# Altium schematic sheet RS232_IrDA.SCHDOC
size A4; Revision: B.2
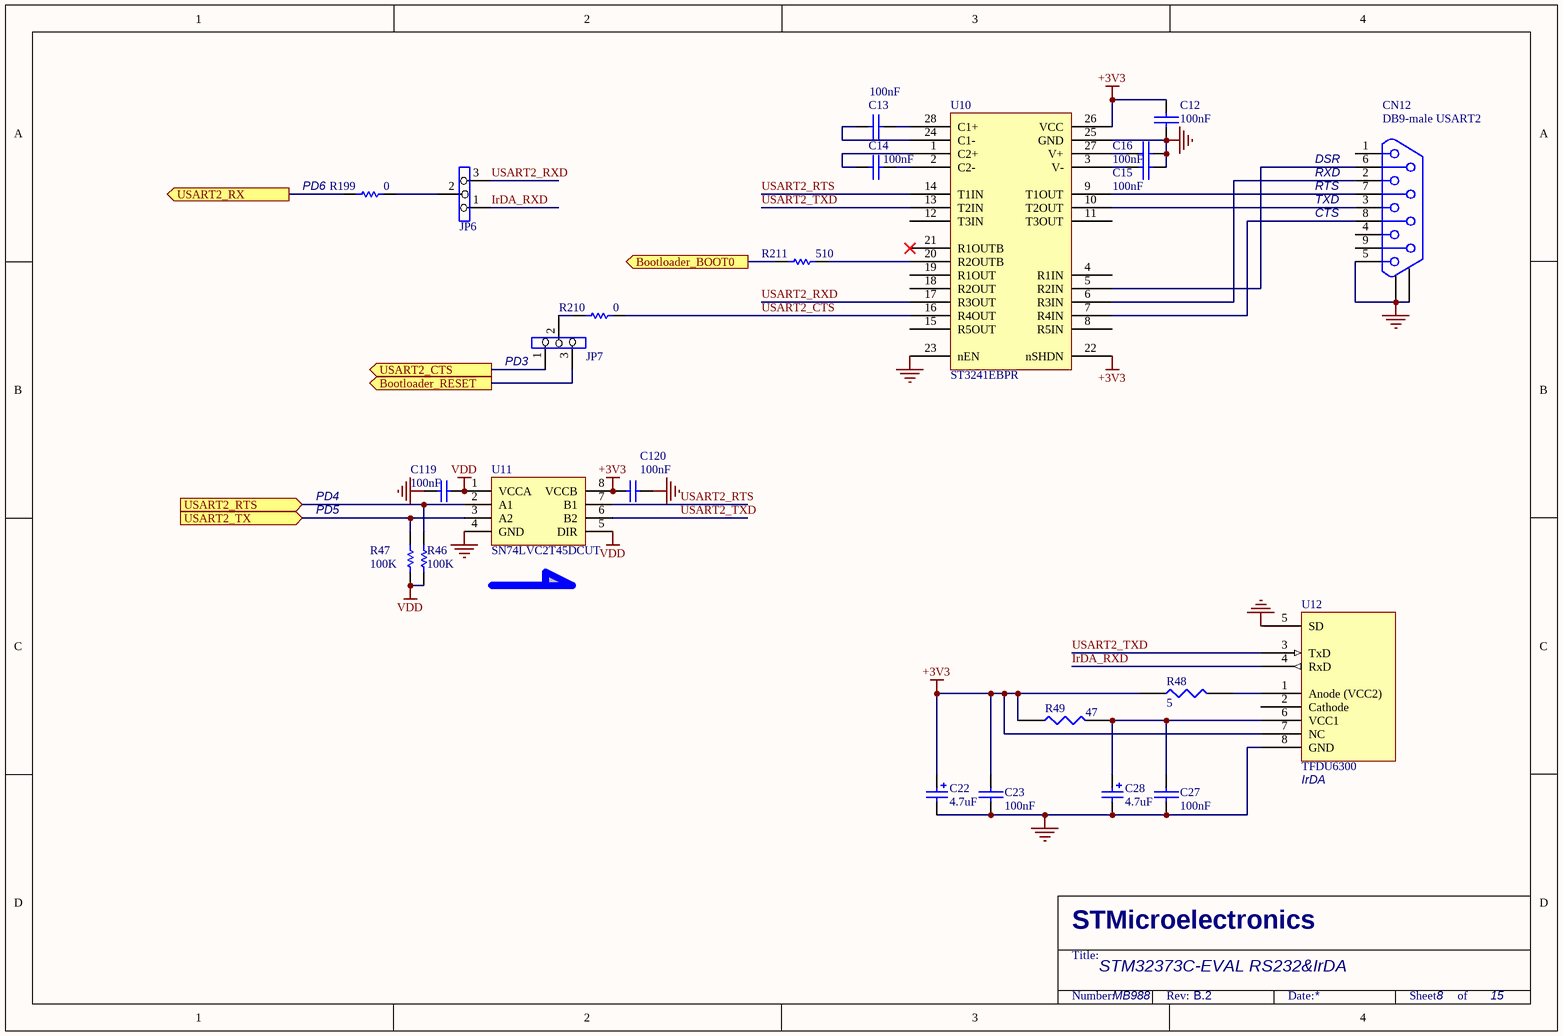
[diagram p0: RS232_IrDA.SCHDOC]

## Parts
C12  100nF  [0603C]
C13  100nF  [0603C]
C14  100nF  [0603C]
C15  100nF  [0603C]
C16  100nF  [0603C]
C22  4.7uF  [TAN-A]
C23  100nF  [0603C]
C27  100nF  [0603C]
C28  4.7uF  [TAN-A]
C119  100nF  [0603C]
C120  100nF  [0603C]
CN12  DB9-male USART2  [DB9/M]
JP6  (no value)  [SIP3]
JP7  (no value)  [SIP3]
R46  100K  [0603R]
R47  100K  [0603R]
R48  5  [0603R]
R49  47  [0603R]
R199  0  [0603R]
R210  0  [0603R]
R211  510  [0603R]
U10  ST3241EBPR  [SSOP28]
U11  SN74LVC2T45DCUT  [VSSOP8]
U12  TFDU6300  [IR_VISHAY3]

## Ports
Bootloader_BOOT0 (out), Bootloader_RESET (out), USART2_CTS (out), USART2_RTS (in), USART2_RX (out), USART2_TX (in)

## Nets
+3V3: C12.2 C22.1 C23.1 C120.2 R48.1 R49.1 U10.22(nSHDN) U10.26(VCC) U11.8(VCCB) U12.7(NC)
GND: C12.1 C15.2 C16.2 C22.2 C23.2 C27.2 C28.2 C119.1 C120.1 CN12.0 CN12.5 U10.23(nEN) U10.25(GND) U11.4(GND) U12.5(SD) U12.8(GND)
VDD: C119.2 R46.2 R47.2 U11.1(VCCA) U11.5(DIR)
Bootloader_BOOT0: R211.1 ; port Bootloader_BOOT0
Bootloader_RESET: JP7.3 ; port Bootloader_RESET
IrDA_RXD: JP6.1 U12.4(RxD)
USART2_CTS: JP7.1 ; port USART2_CTS
USART2_CTS: R210.2 U10.16(R4OUT)  [a separate net that carries the same name]
USART2_RTS: U10.14(T1IN) U11.7(B1)
USART2_RTS: R46.1 U11.2(A1) ; port USART2_RTS  [a separate net that carries the same name]
USART2_RX: R199.1 ; port USART2_RX
USART2_RXD: JP6.3 U10.17(R3OUT)
USART2_TX: R47.1 U11.3(A2) ; port USART2_TX
USART2_TXD: U10.13(T2IN) U11.6(B2) U12.3(TxD)
NetC13_1: C13.1 U10.24(C1-)
NetC13_2: C13.2 U10.28(C1+)
NetC14_1: C14.1 U10.1(C2+)
NetC14_2: C14.2 U10.2(C2-)
NetC15_1: C15.1 U10.3(V-)
NetC16_1: C16.1 U10.27(V+)
NetC27_1: C27.1 C28.1 R49.2 U12.6(VCC1)
NetCN12_2: CN12.2 U10.6(R3IN)
NetCN12_3: CN12.3 U10.10(T2OUT)
NetCN12_6: CN12.6 U10.5(R2IN)
NetCN12_7: CN12.7 U10.9(T1OUT)
NetCN12_8: CN12.8 U10.7(R4IN)
NetJP6_2: JP6.2 R199.2
NetJP7_2: JP7.2 R210.1
NetR48_2: R48.2 U12.1(Anode_(VCC2))
NetR211_2: R211.2 U10.20(R2OUTB)

Not connected (* = marked no-connect by the designer): CN12 1 4 9; U10 4(R1IN) 8(R5IN) 11(T3OUT) 12(T3IN) 15(R5OUT) 18(R2OUT) 19(R1OUT) 21(R1OUTB)*; U12 2(Cathode)

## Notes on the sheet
- (near CN12) RXD
- (near CN12) DSR
- (near R199) PD6
- (near CN12) RTS
- (near CN12) TXD
- (near CN12) CTS
- (near JP7) PD3
- PD5
- PD4
- (near U12) IrDA
- STM32373C-EVAL RS232&IrDA
- MB988
- 8
- 15

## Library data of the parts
C12-C16 C23 C27 = CAP: Capacitor
C22 C28 = Cap Pol1: Polarized Capacitor (Radial); Value: 100pF
C119 C120 = CAP: Capacitor; Value: 100pF
CN12 = DB9
JP6 JP7 = Jumper3
R46 R47 R199 R210 R211 = Res1: Resistor; Value: 1K
R48 R49 = RES1
U10 = ST3241
U12 = TFDU4300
